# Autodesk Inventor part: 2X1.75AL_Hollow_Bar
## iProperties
Shininess: 64.0
Length Units: 11272
Angle Units: 11279
Time Units: 11290
Mass Units: 11286
Length Display Precision: 3
Angle Display Precision: 2
Compacted: True
Part Number: 2X1.75AL_Hollow_Bar
Document SubType Name: Modeling
Created: 2004-08
Designer: John Blackburn
Manufacturer: Standard
Standards Organization: Custom
Material: Aluminum-6061
Density: 0.0
Volumn: 0.0
Area: 0.0
PropertySet Name: Model Information
Control State: 0
Master: False
Checked Out: False
Author: John Blackburn
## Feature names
1. Extrusion1
2. Extrusion2
3. Hole1
